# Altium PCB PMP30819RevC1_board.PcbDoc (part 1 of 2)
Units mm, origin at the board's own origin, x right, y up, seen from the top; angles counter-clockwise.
Board outline 73.66 x 66.04 mm, 4 copper layers (Top Layer, Layer 1, Layer 2, Bottom Layer), stack 1.787 mm thick; 100 components, 30 nets, 255 pads, 105 vias.
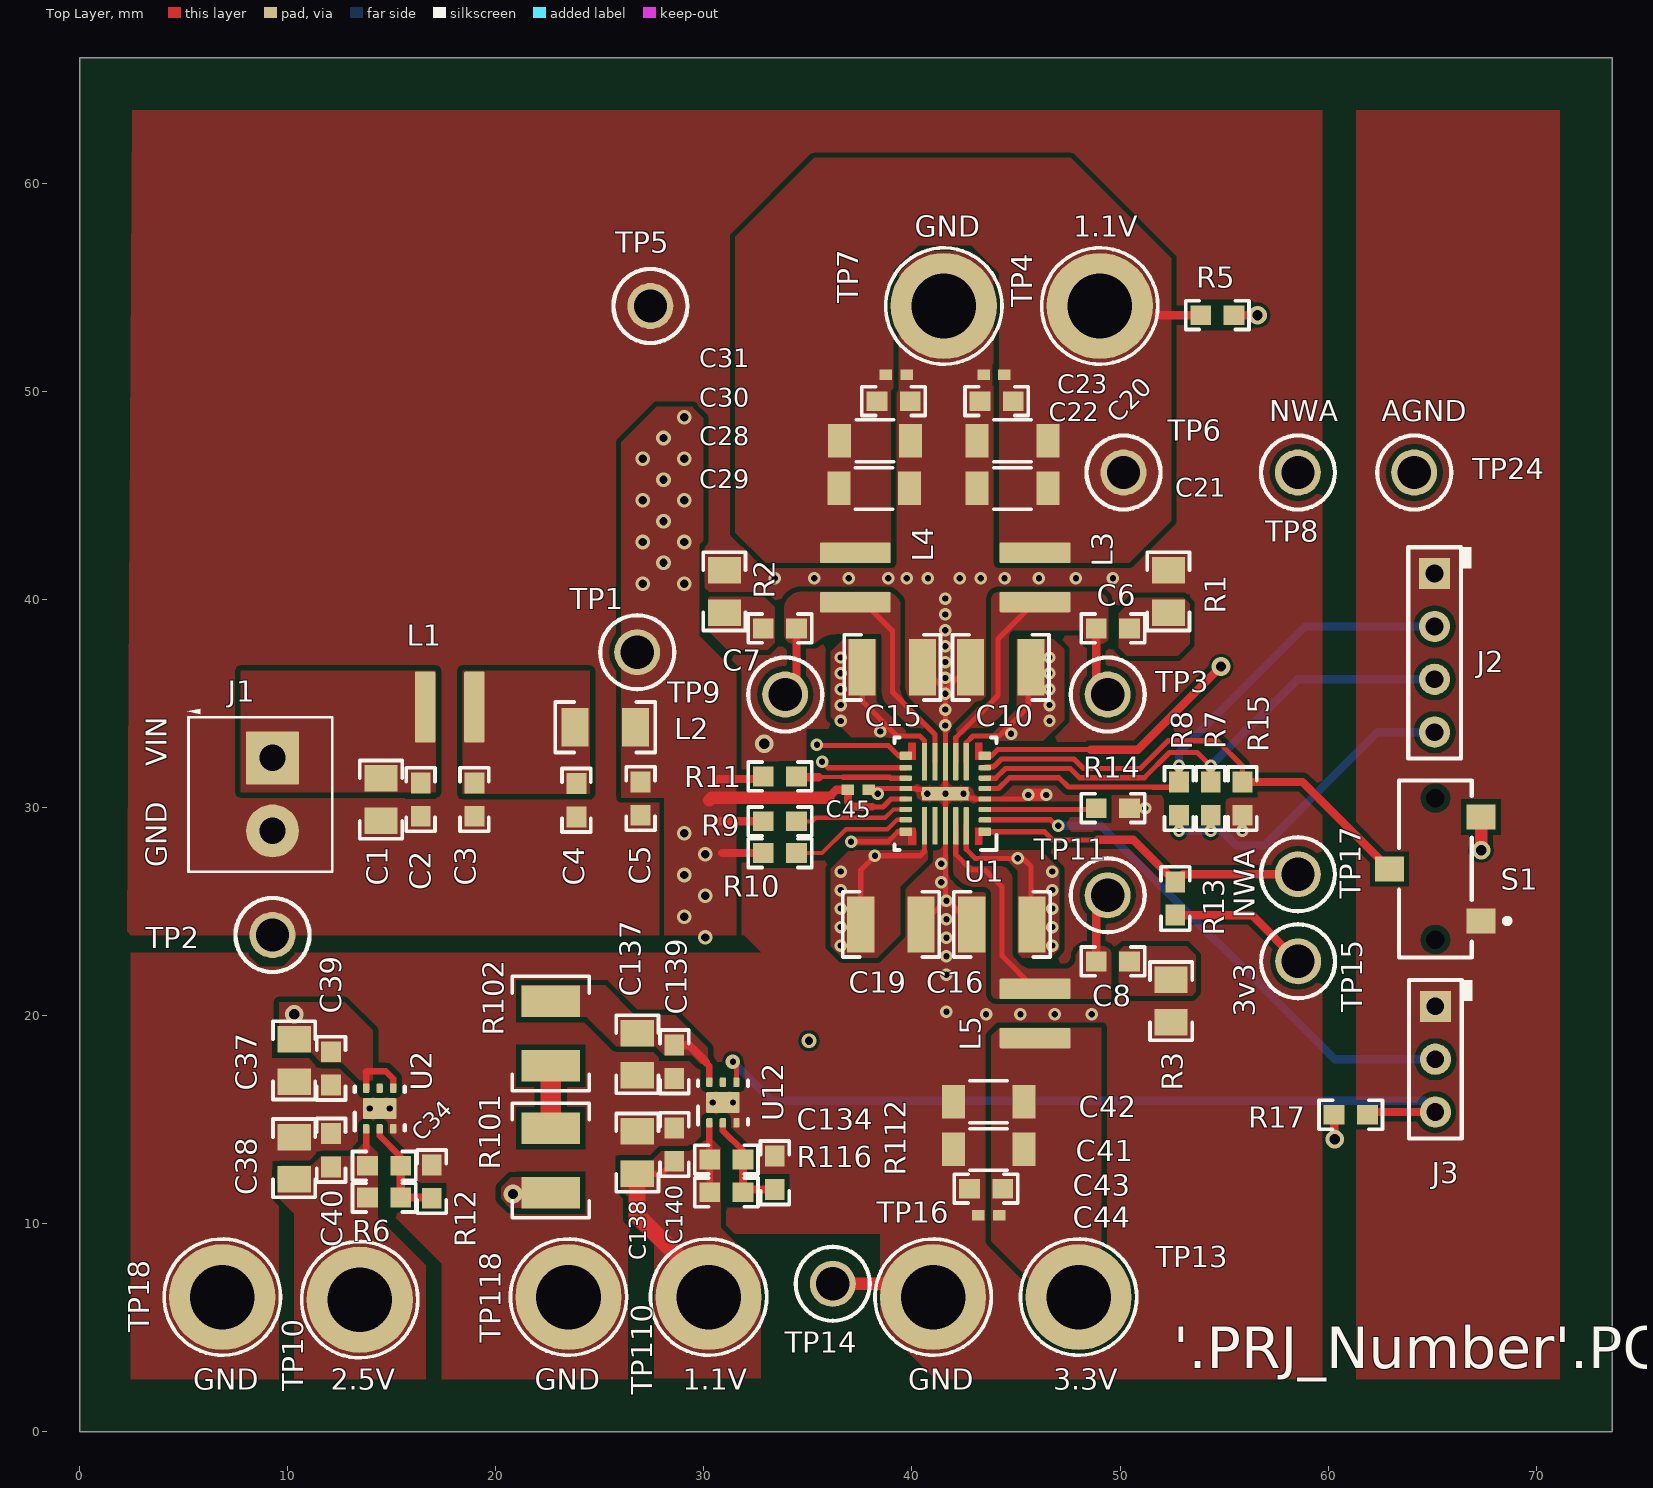
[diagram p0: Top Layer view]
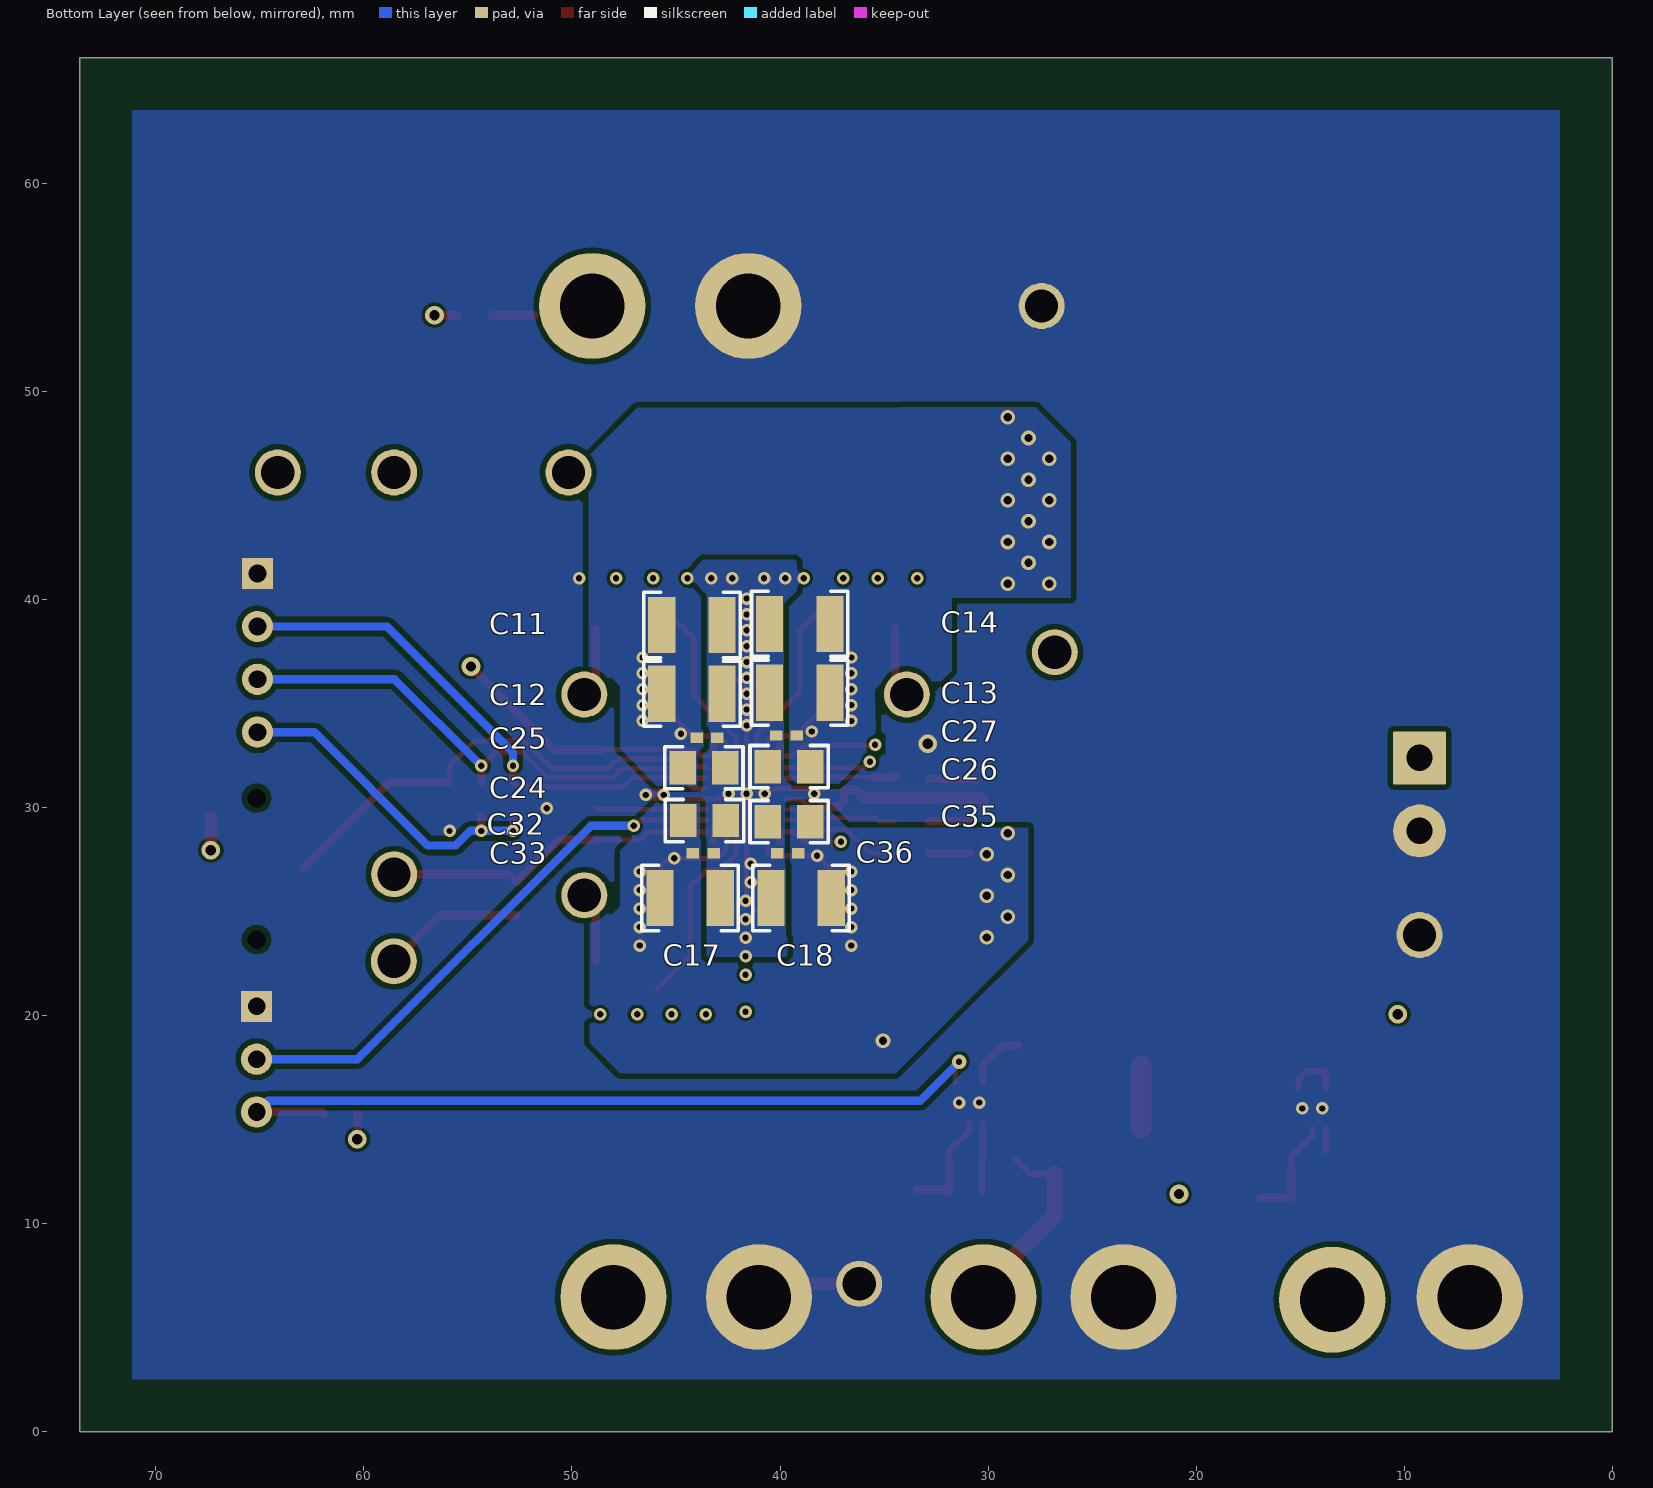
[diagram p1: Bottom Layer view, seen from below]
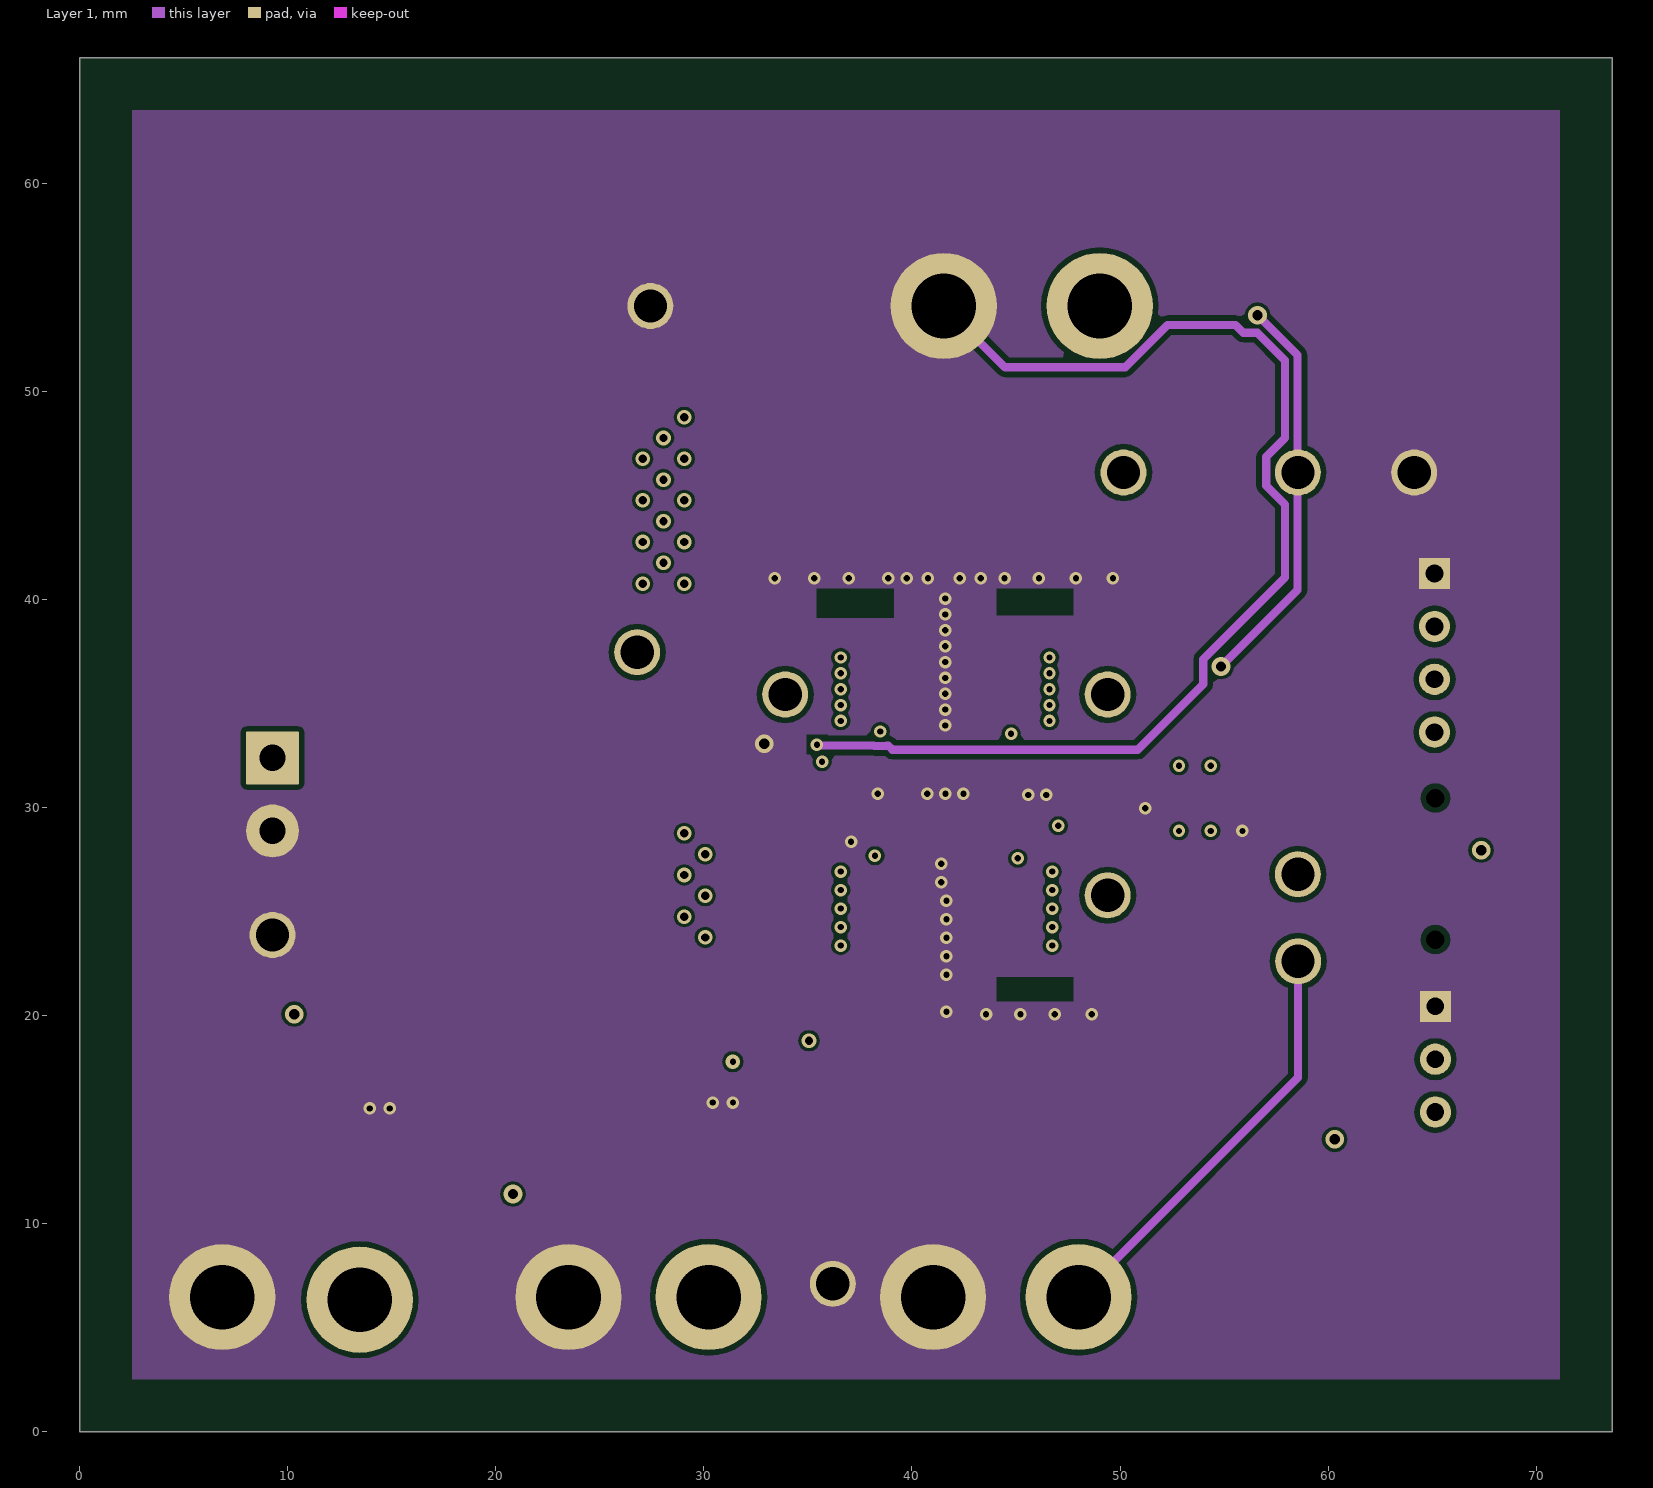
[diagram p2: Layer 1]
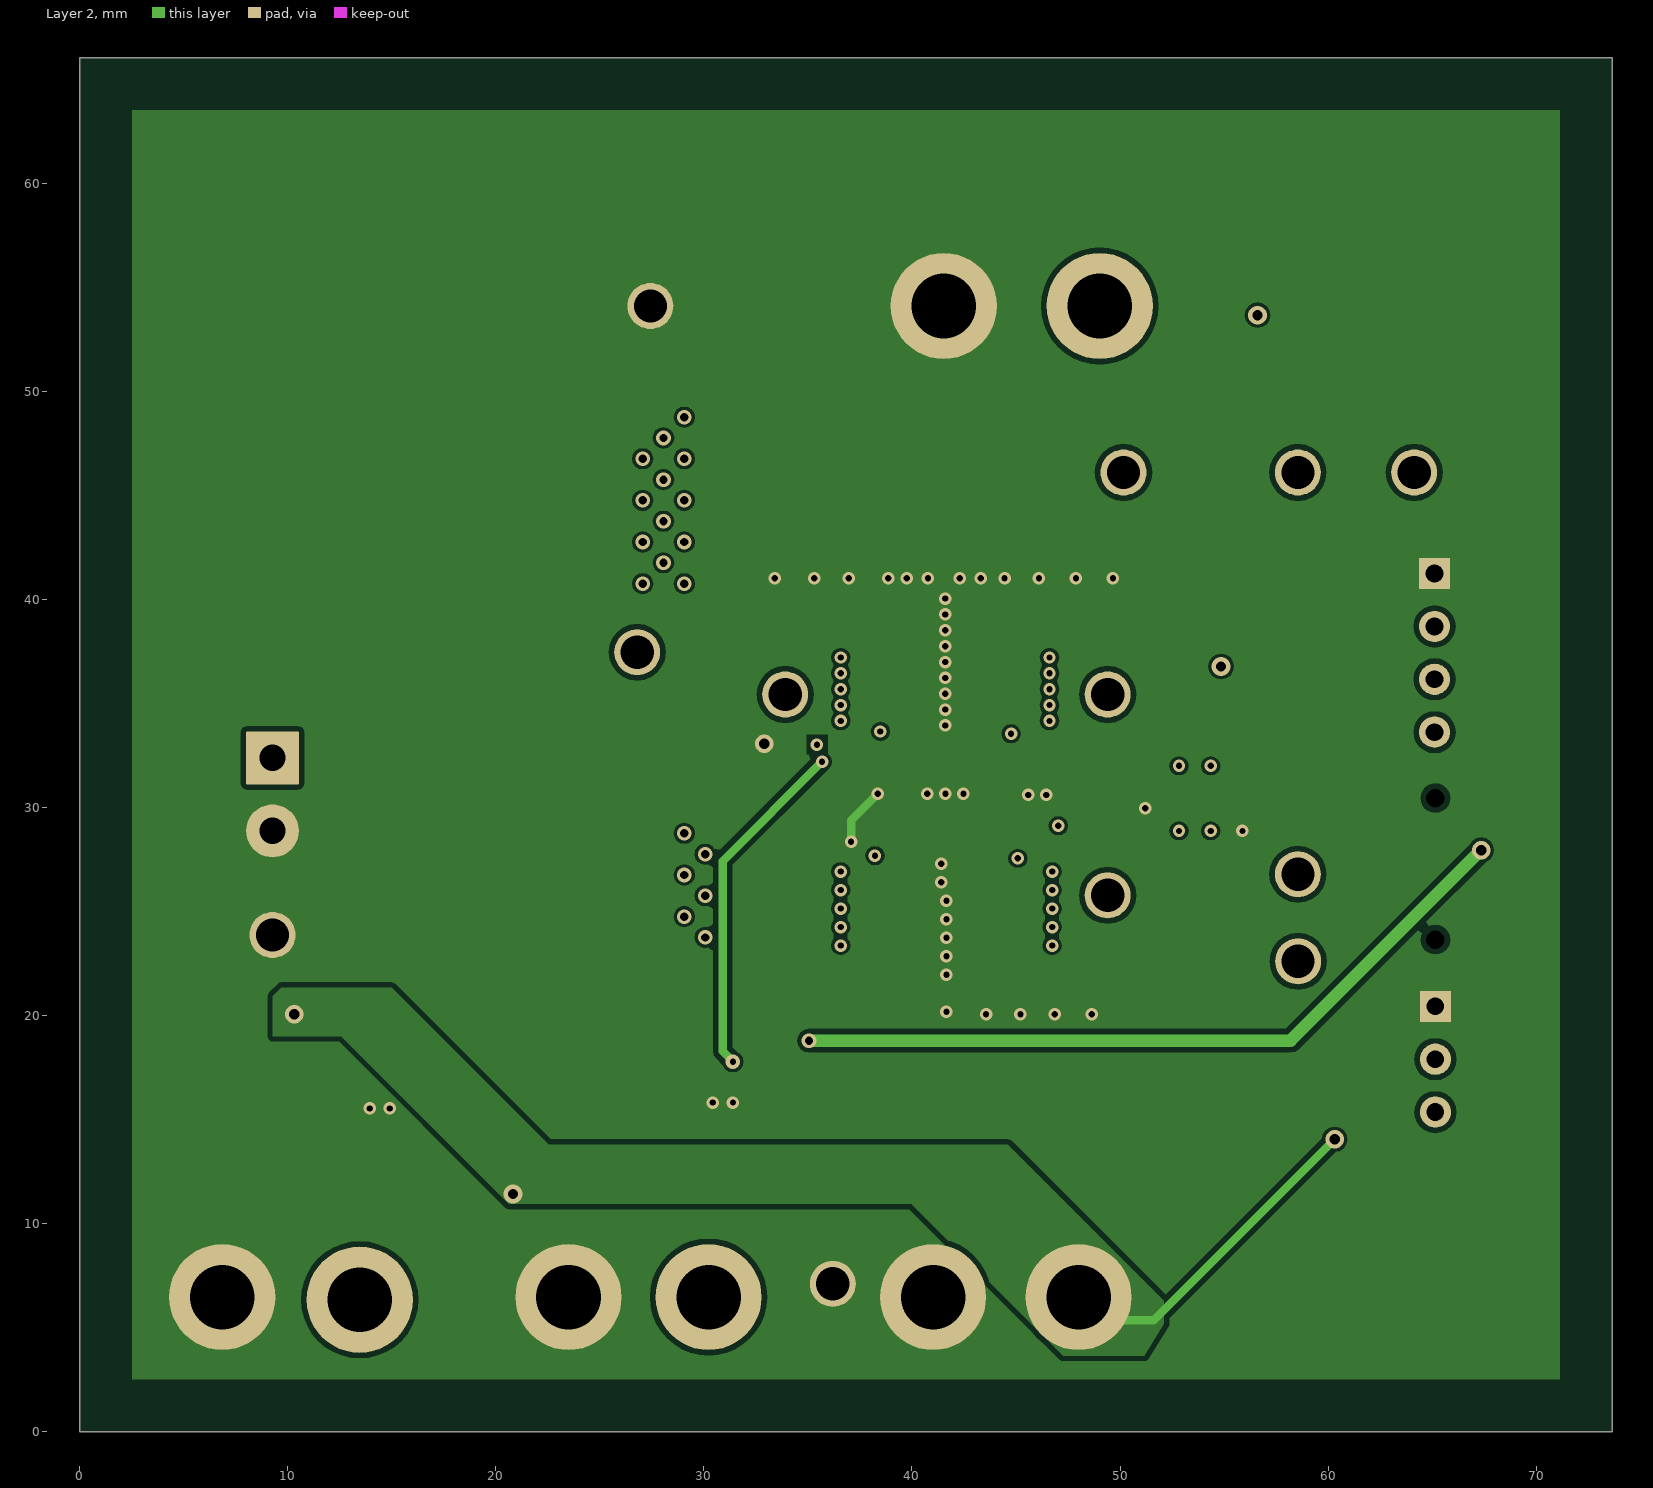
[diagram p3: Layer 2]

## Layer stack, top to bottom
Top Solder: solder mask 0.0102, Solder Resist, Dk 3.5
Top Layer: signal copper 0.0356
Dielectric 1: prepreg 0.0711, PP-006, Dk 4.1
Layer 1: signal copper 0.035
Dielectric1: core 1.5037, FR-4, Dk 4.8
Layer 2: signal copper 0.035
Dielectric 2: prepreg 0.0711, PP-006, Dk 4.1
Bottom Layer: signal copper 0.0356
Bottom Solder: solder mask 0.0102, Solder Resist, Dk 3.5

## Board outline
0,0 0,66.04 73.66,66.04 73.66,0

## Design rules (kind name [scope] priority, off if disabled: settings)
AcuteAngle [All] p1: minimum=4.50000000000000E+0001 checktracksonly=FALSE
AssemblyTestPointUsage [All] p1: valid=2
BoardOutlineClearance BoardOutlineClearance_MountingHoles [OnCopper and InComponentClass('Mounting Holes')] p1: gap=1 ignorepadtopadclearanceinfootprint=FALSE
BoardOutlineClearance BoardOutlineClearance_Poly [OnCopper and IsPoly] p2: gap=0.635 ignorepadtopadclearanceinfootprint=FALSE
BoardOutlineClearance [OnCopper and Not InComponentClass('Logo') and not InComponentClass('FiducialMark') and not InRegion(1000,500,4000,800) and not InPoly] p3: gap=1.905 ignorepadtopadclearanceinfootprint=FALSE
Clearance Clearance_Keepouts [((IsTrack Or IsArc) And Not InPoly) And IsFree and IsKeepOut vs ((IsTrack Or IsArc) And Not InPoly) And IsFree and IsKeepOut] p1: gap=0 ignorepadtopadclearanceinfootprint=FALSE
Clearance Clearance_Poly [InPolygon] p2: gap=0.254 ignorepadtopadclearanceinfootprint=TRUE except(0.15: Via-Fill Via-Poly Via-Region)
Clearance Clearance_FiducialMark [IsKeepOut and InComponentClass('FiducialMark') vs IsPad and InComponentClass('FiducialMark')] p3: gap=0 ignorepadtopadclearanceinfootprint=FALSE
Clearance [All] p4: gap=0.2 ignorepadtopadclearanceinfootprint=TRUE
ComponentClearance ComponentClearance_MountingHoles_FiducialMarks [InComponentClass('Mounting Holes') vs InComponentClass('FiducialMark')] p1: gap=1.27 collisioncheckmode=3 verticalgap=0.254 showdistances=FALSE
ComponentClearance ComponentClearance_Shunt [InComponentClass('Header') vs InComponentClass('Shunt')] p2: gap=0 collisioncheckmode=3 verticalgap=0 showdistances=FALSE
ComponentClearance ComponentClearance_Logo [InComponentClass('Logo')] p3: gap=1.27 collisioncheckmode=3 verticalgap=0.254 showdistances=FALSE
ComponentClearance ComponentClearance_ScrewToNut [(HasFootprint('NY PMS 440 0025 PH')) vs (HasFootprint('Keystone_1902C'))] p4: gap=0.127 collisioncheckmode=3 verticalgap=0.254 showdistances=FALSE
ComponentClearance ComponentClearance_MountingHoles [InComponentClass('Mounting Holes')] p5: gap=6.35 collisioncheckmode=3 verticalgap=2540 showdistances=FALSE
ComponentClearance ComponentClearance_SmallPassives [HasFootprint('0201*') or HasFootprint('0402*') or HasFootprint('0508') or HasFootprint('0603*') or HasFootprint('0612') or HasFootprint('0805*') or HasFootprint('0815*') or HasFootprint('0830*') or HasFootprint('1206*') or HasFootprint('1210*') or HasFootprint('1808*') or HasFootprint('1812*') or HasFootprint('1825*') or HasFootprint('2010*') or HasFootprint('2220*') or HasFootprint('2225*') or HasFootprint('2512*') or HasFootprint('2728*') or HasFootprint('3518*') vs HasFootprint('0201*') or HasFootprint('0402*') or HasFootprint('0508') or HasFootprint('0603*') or HasFootprint('0612') or HasFootprint('0805*') or HasFootprint('0815*') or HasFootprint('0830*') or HasFootprint('1206*') or HasFootprint('1210*') or HasFootprint('1808*') or HasFootprint('1812*') or HasFootprint('1825*') or HasFootprint('2010*') or HasFootprint('2220*') or HasFootprint('2225*') or HasFootprint('2512*') or HasFootprint('2728*') or HasFootprint('3518*')] p6: gap=0.38 collisioncheckmode=3 verticalgap=0.254 showdistances=FALSE
ComponentClearance ComponentClearance_THtoSMT [IsThruComponent vs IsSMTComponent] p7: gap=1.016 collisioncheckmode=3 verticalgap=0.762 showdistances=FALSE
ComponentClearance ComponentClearance_THtoTH [IsThruComponent vs IsThruComponent] p8: gap=0.762 collisioncheckmode=3 verticalgap=0.762 showdistances=FALSE
ComponentClearance [All] p9: gap=0.762 collisioncheckmode=3 verticalgap=0.254 showdistances=FALSE
DiffPairsRouting [All] p1: maxlimit=2.54 minlimit=0.254 mostfreqgap=0.254 toplayer_minwidth=0.381 toplayer_maxwidth=0.381 toplayer_prefwidth=0.381 midlayer1_minwidth=0.381 midlayer1_maxwidth=0.381 midlayer1_prefwidth=0.381 midlayer2_minwidth=0.381 midlayer2_maxwidth=0.381 midlayer2_prefwidth=0.381 bottomlayer_minwidth=0.381 bottomlayer_maxwidth=0.381 bottomlayer_prefwidth=0.381 maxuncoupledlength=25.4
FabricationTestPointUsage TestPointUsage [All] p1: valid=2 allowmultiple=FALSE
FabricationTestpoint Testpoint [All] p1: side=3 testpointundercomponent=TRUE minsize=1.016 maxsize=2.54 preferedsize=1.524 minholesize=0 maxholesize=1.016 preferedholesize=0.813 testpointgrid=0.025 allowsidetop=TRUE allowsidebottom=TRUE usegrid=TRUE gridtolerance=0
FanoutControl Fanout_LCC [IsLCC] p1: bgadir=Out bgaviamode=Centered fanoutstyle=Auto fanoutdirection=Alternating viagrid=0.025 // Fanout_LCC (Default Rule)
FanoutControl Fanout_BGA [IsBGA] p2: bgadir=Out bgaviamode=Centered fanoutstyle=Auto fanoutdirection=Alternating viagrid=0.025 // Fanout_BGA (Default Rule)
FanoutControl Fanout_Default [All] p4: bgadir=Out bgaviamode=Centered fanoutstyle=Auto fanoutdirection=Alternating viagrid=0.025 // Fanout_Default (Default Rule)
FanoutControl Fanout_Small [(CompPinCount < 5)] p5: bgadir=Out bgaviamode=Centered fanoutstyle=Auto fanoutdirection=OutThenIn viagrid=0.025 // Fanout_Small (Default Rule)
HoleSize [All] p1: absolutevalues=TRUE maxlimit=6.375 minlimit=0.3 maxpercent=80.000 minpercent=20.000
MinimumAnnularRing MinimumAnnularRing_ThermalPadVias [IsVia and InAnyComponent] p1: minimumring=0.15
MinimumAnnularRing [All] p2: minimumring=0.15
MinimumSolderMaskSliver MinimumSolderMaskSliver_Logo [InComponentClass('Logo') vs InComponentClass('Logo')] p1: minsoldermaskwidth=0.018
MinimumSolderMaskSliver [All] p2: minsoldermaskwidth=0.1
PlaneConnect [All] p1: planeconnectstyle=Relief reliefexpansion=0.254 reliefentries=4 reliefconductorwidth=0.254 reliefairgap=0.254
PolygonConnect PolygonConnect_TP24 [InComponent('TP24') vs OnBottomLayer or OnTopLayer or OnLayer('Layer 2')] p1: thpad.connectstyle=NoConnect thpad.reliefconductorwidth=0.254 thpad.reliefentries=4 thpad.polygonreliefangle="90 Angle" thpad.airgapwidth=0.254 smdpad.connectstyle=Direct smdpad.reliefconductorwidth=0.254 smdpad.reliefentries=4 smdpad.polygonreliefangle="90 Angle" smdpad.airgapwidth=0.254 via.connectstyle=Direct via.reliefconductorwidth=0.254 via.reliefentries=4 via.polygonreliefangle="90 Angle" via.airgapwidth=0.254
PolygonConnect [All] p2: connectstyle=Direct reliefconductorwidth=0.254 reliefentries=4 polygonreliefangle="90 Angle" airgapwidth=0.254
RoutingVias ThermalPadVias [IsVia and InAnyComponent] p1: holewidth=0.2 width=0.5 viastyle="Through Hole" minholewidth=0.2 minwidth=0.5 maxholewidth=0.33 maxwidth=0.6
RoutingVias [All] p2: holewidth=0.5 width=0.9 viastyle="Through Hole" minholewidth=0.3 minwidth=0.6 maxholewidth=1.016 maxwidth=1.651
SilkToBoardRegionClearance [Not ((IsComment or IsDesignator) And (Hide <> 'False')) and not InRegion(1000,500,4000,800)] p1:
SilkToSilkClearance SilkToSilkClearance_Pb-FreeLogo [(HasFootprint('Pb-Free_Overlay_Medium') OR HasFootprint('Pb-Free_Overlay_Small')) vs (HasFootprint('Pb-Free_Overlay_Medium') OR HasFootprint('Pb-Free_Overlay_Small'))] p1: silktosilkclearance=0
SilkToSilkClearance [All] p2: silktosilkclearance=0.1
SilkToSolderMaskClearance SilkToComponentPadClearance [(IsPad or IsFill or IsRegion) and InAnycomponent] p1: minsilkscreentomaskgap=0.127 clearancetoexposedcopper=TRUE
SilkToSolderMaskClearance "Silk to Solder Mask Opening" [All] p2: minsilkscreentomaskgap=0.1 clearancetoexposedcopper=FALSE
SolderMaskExpansion [All] p1: expansion=0.05 istentingtop=FALSE
UnRoutedNet [All] p1: checkbadconnections=TRUE
Width [All] p1: maxlimit=2.54 minlimit=0.152 preferedwidth=0.254 checkconnectedcopper=TRUE
14 further rules are at their usual default settings.

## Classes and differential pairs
component class Header: J2 J3

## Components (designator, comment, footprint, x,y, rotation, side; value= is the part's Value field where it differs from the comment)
C1 "CL21B106KOQNNNE" 0805_HV 14.486,30.386 r270 top value=10uF
C2 "GRM188R71C105KA12D" 0603 16.391,30.386 r270 top value=1uF
C3 "GRM188R71C105KA12D" 0603 18.973,30.386 r270 top value=1uF
C4 "GRM188R71C103KA01D" 0603 23.876,30.353 r270 top value=0.01uF
C5 "GRM188R71C103KA01D" 0603 26.958,30.431 r270 top value=0.01uF
C6 "GRM188R71H391KA01D" 0603 49.657,38.608 r0 top value=390pF
C7 "GRM188R71H391KA01D" 0603 33.655,38.608 r180 top value=390pF
C8 "GRM188R71H391KA01D" 0603 49.657,22.606 r0 top value=390pF
C10 "LMK325B7476MM-TR" 1210_270 44.264,36.74 r180 top value=47uF
C11 "LMK325B7476MM-TR" 1210_270 44.234,38.772 r180 bottom value=47uF
C12 "LMK325B7476MM-TR" 1210_270 44.234,35.47 r180 bottom value=47uF
C13 "LMK325B7476MM-TR" 1210_270 39.057,35.521 r0 bottom value=47uF
C14 "LMK325B7476MM-TR" 1210_270 39.057,38.823 r0 bottom value=47uF
C15 "LMK325B7476MM-TR" 1210_270 39.057,36.74 r180 top value=47uF
C16 "LMK325B7476MM-TR" 1210_270 44.323,24.384 r180 top value=47uF
C17 "LMK325B7476MM-TR" 1210_270 44.323,25.654 r180 bottom value=47uF
C18 "LMK325B7476MM-TR" 1210_270 38.989,25.654 r0 bottom value=47uF
C19 "LMK325B7476MM-TR" 1210_270 38.989,24.384 r0 top value=47uF
C20 "GRJ31CR71A226KE12L" 1206_190 44.831,47.625 r180 top value=22uF
C21 "GRJ31CR71A226KE12L" 1206_190 44.831,45.339 r180 top value=22uF
C22 "GCM188R71C104KA37J" 0603 44.069,49.53 r0 top value=0.1uF
C23 "CGA2B2X7R1H332K050BA" 0402L 43.942,50.8 r180 top value=3300pF
C24 "CL21B106KOQNNNE" 0805_HV 43.655,31.913 r180 bottom value=10uF
C25 "C0402C104K4RACAUTO" 0402L 43.505,33.363 r0 bottom value=0.1uF
C26 "CL21B106KOQNNNE" 0805_HV 39.565,31.965 r0 bottom value=10uF
C27 "C0402C104K4RACAUTO" 0402L 39.692,33.463 r0 bottom value=0.1uF
C28 "GRJ31CR71A226KE12L" 1206_190 38.227,47.625 r0 top value=22uF
C29 "GRJ31CR71A226KE12L" 1206_190 38.184,45.339 r0 top value=22uF
C30 "GCM188R71C104KA37J" 0603 39.116,49.53 r180 top value=0.1uF
C31 "CGA2B2X7R1H332K050BA" 0402L 39.243,50.8 r0 top value=3300pF
C32 "CL21B106KOQNNNE" 0805_HV 43.629,29.374 r180 bottom value=10uF
C33 "C0402C104K4RACAUTO" 0402L 43.688,27.813 r0 bottom value=0.1uF
C34 "GRM188R71C103KA01D" 0603 14.639,12.784 r0 top value=0.01uF
C35 "CL21B106KOQNNNE" 0805_HV 39.565,29.323 r0 bottom value=10uF
C36 "C0402C104K4RACAUTO" 0402L 39.624,27.813 r0 bottom value=0.1uF
C37 "CL21B106KOQNNNE" 0805_HV 10.311,17.849 r270 top value=10uF
C38 "CL21B106KOQNNNE" 0805_HV 10.311,13.15 r90 top value=10uF
C39 "GCM188R71C104KA37J" 0603 12.089,17.468 r90 top value=0.1uF
C40 "GCM188R71C104KA37J" 0603 12.089,13.531 r270 top value=0.1uF
C41 "GRJ31CR71A226KE12L" 1206_190 43.689,13.576 r180 top value=22uF
C42 "GRJ31CR71A226KE12L" 1206_190 43.689,15.862 r180 top value=22uF
C43 "GCM188R71C104KA37J" 0603 43.561,11.684 r0 top value=0.1uF
C44 "CGA2B2X7R1H332K050BA" 0402L 43.688,10.414 r180 top value=3300pF
C45 "C0402C104K4RACAUTO" 0402L 37.424,30.861 r0 top value=0.1uF
C134 "GRM188R71C103KA01D" 0603 31.082,13.085 r0 top value=0.01uF
C137 "CL21B106KOQNNNE" 0805_HV 26.804,18.145 r270 top value=10uF
C138 "CL21B106KOQNNNE" 0805_HV 26.804,13.423 r90 top value=10uF
C139 "GCM188R71C104KA37J" 0603 28.582,17.784 r90 top value=0.1uF
C140 "GCM188R71C104KA37J" 0603 28.582,13.804 r270 top value=0.1uF
J1 "ED555/2DS" TERM_BLK_ED555-2DS 9.271,32.385 r270 top
J2 "800-10-004-10-001000" Mill-Max_800-10-004-10-001000 65.113,37.434 r270 top
J3 "800-10-003-10-001000" Mill-Max_800-10-003-10-001000 65.151,17.907 r270 top
L1 "XGL4020-471MEC" FP-XGL4020-471MEC_SMT_4MM0_4MM0-MFG 17.788,34.831 r0 top
L2 "HI1206T161R-10" 1206 25.258,33.86 r0 top value="160 ohm"
L3 "XGL4020-471MEC" FP-XGL4020-471MEC_SMT_4MM0_4MM0-MFG 45.915,41.058 r90 top
L4 "XGL4020-471MEC" FP-XGL4020-471MEC_SMT_4MM0_4MM0-MFG 37.279,41.058 r90 top
L5 "XGL4020-471MEC" FP-XGL4020-471MEC_SMT_4MM0_4MM0-MFG 45.915,20.103 r270 top
R1 "CRCW08053R90JNEA" 0805_HV 52.324,40.386 r270 top value=3.9
R2 "CRCW08053R90JNEA" 0805_HV 30.988,40.386 r270 top value=3.9
R3 "CRCW08053R90JNEA" 0805_HV 52.451,20.701 r90 top value=3.9
R5 "CRCW060347R0JNEA" 0603 54.674,53.662 r180 top value=47
R6 "CRCW060319K6FKEA" 0603 14.639,11.26 r180 top value=19.6k
R7 "CRCW06032K20JNEA" 0603 54.356,30.428 r90 top value=2.2k
R8 "CRCW06032K20JNEA" 0603 52.832,30.428 r90 top value=2.2k
R9 "CRCW0603100KFKEA" 0603 33.655,29.337 r0 top value=100k
R10 "CRCW0603100KFKEA" 0603 33.655,27.813 r0 top value=100k
R11 "DNP" 0603 33.655,31.496 r0 top value=100k
R12 "CRCW06035K49FKEA" 0603 16.925,12.022 r270 top value=5.49k
R13 "CRCW060347R0JNEA" 0603 52.656,25.63 r270 top value=47
R14 "CRCW060310K0JNEA" 0603 49.657,29.972 r0 top value=10k
R15 "DNP" 0603 55.88,30.428 r90 top value=100k
R17 "CRCW060310K0JNEA" 0603 61.087,15.24 r180 top value=10k
R101 "ERJ-14BQF2R0U" 1210M 22.639,13.044 r90 top value=2.00
R102 "ERJ-14BQF2R0U" 1210M 22.639,19.14 r90 top value=2.00
R112 "CRCW06035K49FKEA" 0603 33.408,12.45 r270 top value=5.49k
R116 "CRCW06035K49FKEA" 0603 31.082,11.51 r180 top value=5.49k
S1 "CL-SB-12B-01T" SW_CL-SB-12B-01 65.151,27.051 r180 top
TP1 "5010" Keystone5010 26.797,37.465 r0 top
TP2 "5011" Keystone5011 9.271,23.876 r0 top
TP3 "SW_0" Keystone5012 49.403,35.433 r180 top
TP4 "1.1VD" Keystone1503-2 49.022,54.102 r180 top value=Double
TP5 "GND" Keystone5011 27.433,54.102 r0 top
TP6 "1V1D" Keystone5010 50.165,46.101 r180 top
TP7 "GND" Keystone1503-2 41.529,54.102 r180 top value=Double
TP8 "5014" Keystone5014 58.547,46.101 r180 top
TP9 "SW_1" Keystone5012 33.909,35.433 r180 top
TP10 "2.5VA" Keystone1503-2 13.462,6.35 r180 top value=Double
TP11 "SW_2" Keystone5012 49.403,25.781 r180 top
TP13 "3.3V" Keystone1503-2 48.006,6.477 r0 top value=Double
TP14 "GND" Keystone5011 36.195,7.112 r0 top
TP15 "3V3" Keystone5010 58.553,22.611 r0 top
TP16 "GND" Keystone1503-2 41.015,6.477 r0 top value=Double
TP17 "5014" Keystone5014 58.547,26.797 r0 top
TP18 "GND" Keystone1503-2 6.858,6.477 r180 top value=Double
TP24 "5011" Keystone5011 64.135,46.101 r0 top
TP110 "1.1VA" Keystone1503-2 30.226,6.477 r0 top value=Double
TP118 "GND" Keystone1503-2 23.495,6.477 r0 top value=Double
U1 "LP87563BRNFRQ1" RNF0026C 41.605,30.663 r180 top
U2 "TPS74501PDRVR" DRV0006A 14.423,15.537 r90 top
U12 "TPS74501PDRVR" DRV0006A 30.913,15.823 r90 top

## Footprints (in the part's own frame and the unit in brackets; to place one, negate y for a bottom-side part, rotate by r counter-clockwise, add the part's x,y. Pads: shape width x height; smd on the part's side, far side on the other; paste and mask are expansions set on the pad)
0402L [mm] "0402 from SM-752 data"
  rect 0.6x0.5 smd: 1(-0.5,0) 2(0.5,0)
  body extent -0.55,-0.3 0.55,0.3, height 0.6
0603 [mm] "0603 from SM-752 data"
  rect 1x0.95 smd: 1(-0.8,0) 2(0.8,0)
  silkscreen extent -1.52,-0.69 1.52,0.69, body extent -0.87,-0.47 0.87,0.47, height 1
0805_HV [mil] "0805 with 30mil clearance between pads"
  rect 50x63 smd: 1(-40,0) 2(40,0)
  silkscreen extent -74,-40 74,40, body extent -43,-29 43,29, height 57
1206 [mm] "1206 from SM-752 data"
  rect 1.3x1.85 smd: 1(-1.45,0) 2(1.45,0)
  silkscreen extent -2.4,-1.21 2.4,1.21, body extent -1.7,-0.9 1.7,0.9, height 1.35
1206_190 [mm] "1206_190"
  rect 1.1x1.6 smd: 1(-1.7,0) 2(1.7,0)
  silkscreen extent -0.9,-1 0.9,1, body extent -1.75,-0.95 1.75,0.95, height 1.9
1210_270 [mm] "1210"
  rect 1.3x2.7 smd: 1(-1.45,0) 2(1.45,0)
  silkscreen extent -2.32,-1.57 2.32,1.57, body extent -1.7,-1.35 1.7,1.35, height 2.7
1210M [mm] "1210 from SM-752 data"
  rect 1.5x2.8 smd: 1(-1.55,0) 2(1.55,0)
  silkscreen extent -2.75,-1.85 2.75,1.85, body extent -1.7,-1.35 1.7,1.35, height 1.35
DRV0006A [mm] "SON, 6-Leads, Body 2x2mm, Pitch 0.65mm, Thermal Pad 1.6x1mm, TI Recommended"
  rrect33% 0.45x0.3 smd: 1(-0.975,0.65) 2(-0.975,0) 3(-0.975,-0.65) 4(0.975,-0.65) 5(0.975,0) 6(0.975,0.65)
  rrect14% 1x0.7 on Top Paste: 7(0,0.45) 7(0,-0.45)
  rrect10% 1x1.6 smd paste-0.5: 7(0,0)
  silkscreen extent -1.05,-1.2 1.05,1.2, body extent -1.05,-1.05 1.05,1.05, height 0.81
FP-XGL4020-471MEC_SMT_4MM0_4MM0-MFG [mm]
  rrect10% 0.98x3.4 smd paste+0 mask+0: 1(-1.185,0) 2(1.185,0)
  body extent -2.25,-2.25 2.25,2.25, height 0.25
Keystone1503-2 [mm] "Double Turret"
  round 5.1 hole 3.1: 1(0,0)
  silkscreen extent -2.79,-2.79 2.79,2.79, body extent -2.4,-2.4 2.38,2.4, height 9.22
Keystone5010 [mil] "Keystone Multipurpose loops"
  round 87 hole 63: 1(0,0)
  silkscreen extent -70,-70 70,70, body extent -63,-63 63,62, height 319
Keystone5011 [mil] "Keystone Multipurpose loops"
  round 87 hole 63: 1(0,0)
  silkscreen extent -70,-70 70,70, body extent -63,-63 63,62, height 319
Keystone5012 [mil] "Keystone Multipurpose loops"
  round 87 hole 63: 1(0,0)
  silkscreen extent -70,-70 70,70, body extent -63,-63 63,62, height 319
Keystone5014 [mil] "Keystone Multipurpose loops"
  round 87 hole 63: 1(0,0)
  silkscreen extent -70,-70 70,70, body extent -63,-63 63,62, height 319
Mill-Max_800-10-003-10-001000 [mm] "Mill-Max"
  rect 1.5x1.5 hole 0.85: 1(-2.54,0)
  round 1.5 hole 0.85: 2(0,0) 3(2.54,0)
  silkscreen extent -3.81,-1.27 3.81,1.78, body extent -3.81,-1.27 3.81,1.27, height 8.13
Mill-Max_800-10-004-10-001000 [mm] "Mill-Max"
  rect 1.5x1.5 hole 0.85: 1(-3.81,0)
  round 1.5 hole 0.85: 2(-1.27,0) 3(1.27,0) 4(3.81,0)
  silkscreen extent -5.08,-1.27 5.08,1.78, body extent -5.08,-1.27 5.08,1.27, height 8.13
RNF0026C [mm] "QFN, 26-Leads, Body 4x4.5mm, Pitch 0.5mm"
  rrect25% 0.6x0.4 smd paste-0.3: 1(-1.9,1.825) 8(-1.9,-1.825) 14(1.9,-1.825) 21(1.9,1.825)
  rrect40% 0.6x0.25 smd paste+0: 2(-1.9,1.25) 3(-1.9,0.75) 4(-1.9,0.25) 5(-1.9,-0.25) 6(-1.9,-0.75) 7(-1.9,-1.25) 15(1.9,-1.25) 16(1.9,-0.75) 17(1.9,-0.25) 18(1.9,0.25) 19(1.9,0.75) 20(1.9,1.25)
  rrect40% 0.25x1.82 smd paste-1: 9(-1,-1.54) 10(-0.5,-1.54) 11(0,-1.54) 12(0.5,-1.54) 13(1,-1.54) 22(1,1.54) 23(0.5,1.54) 24(0,1.54) 25(-0.5,1.54) 26(-1,1.54)
  rrect15% 2.24x0.66 smd paste-1: 27(0,0)
  rrect33% 0.6x0.3 on Top Paste: ""(-1.9,1.775) ""(-1.9,-1.775) ""(1.9,1.775) ""(1.9,-1.775)
  rrect33% 0.3x0.825 on Top Paste: ""(-1.575,2.037) ""(-1.575,-2.037) ""(1.575,2.037) ""(1.575,-2.037)
  rrect40% 0.25x0.81 on Top Paste: ""(-1,1.035) ""(-1,2.045) ""(-1,-2.045) ""(-1,-1.035) ""(-0.5,2.045) ""(-0.5,1.035) ""(-0.5,-1.035) ""(-0.5,-2.045) ""(0,2.045) ""(0,1.035) ""(0,-1.035) ""(0,-2.045) ""(0.5,2.045) ""(0.5,1.035) ""(0.5,-1.035) ""(0.5,-2.045) ""(1,1.035) ""(1,2.045) ""(1,-2.045) ""(1,-1.035)
  rrect15% 0.98x0.66 on Top Paste: ""(-0.59,0) ""(0.59,0)
  Top Layer region: -1.775,-2.4 -1.775,-1.675 -1.771,-1.656 -1.76,-1.64 -1.744,-1.629 -1.725,-1.625 -1.725,-1.625 -1.475,-1.625 -1.456,-1.629 -1.44,-1.64 -1.429,-1.656 -1.425,-1.675 -1.425,-1.675 -1.425,-2.4 -1.429,-2.419 -1.44,-2.435 -1.456,-2.446 -1.475,-2.45 -1.475,-2.45 -1.725,-2.45 -1.744,-2.446 -1.76,-2.435 -1.771,-2.419 -1.775,-2.4
  Top Layer region: 1.425,-2.4 1.425,-1.675 1.429,-1.656 1.44,-1.64 1.456,-1.629 1.475,-1.625 1.475,-1.625 1.725,-1.625 1.744,-1.629 1.76,-1.64 1.771,-1.656 1.775,-1.675 1.775,-1.675 1.775,-2.4 1.771,-2.419 1.76,-2.435 1.744,-2.446 1.725,-2.45 1.725,-2.45 1.475,-2.45 1.456,-2.446 1.44,-2.435 1.429,-2.419 1.425,-2.4
  Top Layer region: 1.425,1.675 1.425,2.4 1.429,2.419 1.44,2.435 1.456,2.446 1.475,2.45 1.475,2.45 1.725,2.45 1.744,2.446 1.76,2.435 1.771,2.419 1.775,2.4 1.775,2.4 1.775,1.675 1.771,1.656 1.76,1.64 1.744,1.629 1.725,1.625 1.725,1.625 1.475,1.625 1.456,1.629 1.44,1.64 1.429,1.656 1.425,1.675
  Top Layer region: -1.775,1.675 -1.775,2.4 -1.771,2.419 -1.76,2.435 -1.744,2.446 -1.725,2.45 -1.725,2.45 -1.475,2.45 -1.456,2.446 -1.44,2.435 -1.429,2.419 -1.425,2.4 -1.425,2.4 -1.425,1.675 -1.429,1.656 -1.44,1.64 -1.456,1.629 -1.475,1.625 -1.475,1.625 -1.725,1.625 -1.744,1.629 -1.76,1.64 -1.771,1.656 -1.775,1.675
  silkscreen extent -2.45,-2.7 2.45,2.7, body extent -2,-2.25 2,2.25, height 0.9
SW_CL-SB-12B-01 [mm] "SMD, 3-Leads, Body 8.5x3.5mm, Pitch 2.5mm"
  rect 1.4x1.2 smd: 1(-2.2,2.5) 2(2.2,0) 3(-2.2,-2.5)
  round 0 hole 0.9 unplated: MH1(0,3.4) MH2(0,-3.4)
  silkscreen extent -3.58,-4.25 1.75,4.25, body extent -1.75,-4.25 1.75,4.25, height 5.5
TERM_BLK_ED555-2DS [mil]
  rrect4% 100x100 hole 50: 1(0,0)
  round 100 hole 50: 2(138,0)
  silkscreen extent -93,-161 215,113, body extent -69,-150 207,106, height 323

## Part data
C1 C24 C26 C32 C35 C37 C38 C137 C138: "CAP, CERM, 10 µF, 16 V,+/- 10%, X7R, 0805", Cap_Case=0805, Manufacturer="Samsung Electro-Mechanics", Supplier Part Number 1=1276-2872-1-ND, TempCo=X7R, Tolerance_%=10, Value2=16V, ValueDisplayed=10µF
C2 C3: "CAP, CERM, 1 µF, 16 V,+/- 10%, X7R, 0603", Cap_Case=0603, Manufacturer=MuRata, Supplier Part Number 1=490-3900-1-ND, TempCo=X7R, Tolerance_%=10, Value1="0.011 ohm", Value2=16V, ValueDisplayed=1µF
C4 C5 C34 C134: "CAP, CERM, 0.01 µF, 16 V,+/- 10%, X7R, 0603", Cap_Case=0603, Manufacturer=MuRata, Supplier Part Number 1=490-1525-1-ND, TempCo=X7R, Tolerance_%=10, Value2=16V, ValueDisplayed=0.01µF
C6 C7 C8: library part CMP-0007452-4, "CAP, CERM, 390 pF, 50 V, +/- 10%, X7R, 0603", Cap_Case=0603, Manufacturer=MuRata, Supplier Part Number 1=490-1555-1-ND, TempCo=X7R, Tolerance_%=10%, Value1=Unknown, Value2=50V, ValueDisplayed=390pF
C10 C11 C12 C13 C14 C15 C16 C17 C18 C19: "CAP, CERM, 47 µF, 10 V,+/- 20%, X7R, 1210", Cap_Case=1210, Manufacturer="Taiyo Yuden", Supplier Part Number 1=587-2783-1-ND, TempCo=X7R, Tolerance_%=20, Value2=10V, ValueDisplayed=47µF
C20 C21 C28 C29 C41 C42: "CAP, CERM, 22 µF, 10 V,+/- 10%, X7R, 1206", Cap_Case=1206, Manufacturer=MuRata, Supplier Part Number 1=490-10937-1-ND, TempCo=X7R, Tolerance_%=10, Value2=10V, ValueDisplayed=22µF
C22 C30 C39 C40 C43 C139 C140: "CAP, CERM, 0.1 µF, 16 V,+/- 10%, X7R, AEC-Q200 Grade 1, 0603", Cap_Case=0603, Manufacturer=MuRata, Supplier Part Number 1=490-8015-1-ND, TempCo=X7R, Tolerance_%=10, Value2=16V, ValueDisplayed=0.1µF
C23 C31 C44: "CAP, CERM, 3300 pF, 50 V,+/- 10%, X7R, AEC-Q200 Grade 1, 0402", Cap_Case=0402, Manufacturer=TDK, Supplier Part Number 1=445-6891-1-ND, TempCo=X7R, Tolerance_%=10, Value1="0.785178 ohm", Value2=50V, ValueDisplayed=3300pF
C25 C27 C33 C36 C45: library part CMP-0006237-2, "CAP, CERM, 0.1 uF, 16 V, +/- 10%, X7R, AEC-Q200 Grade 1, 0402", Cap_Case=0402, Manufacturer=Kemet, Supplier Part Number 1=399-6828-1-ND, TempCo=X7R, Tolerance_%=10%, Value1=Unknown, Value2=16V, ValueDisplayed=0.1uF
J1: library part CMP-0074913-1, "Terminal Block, 3.5mm Pitch, 2x1, TH", Color=Grey, Current_A=6A, Manufacturer="On-Shore Technology", Supplier Part Number 1=ED1514-ND, Voltage_V=150V
J2: "Header, 100mil, 4x1, TH", Manufacturer=Mill-Max, Supplier Part Number 1=ED7204-ND
J3: library part CMP-0055086-1, "Header, 100mil, 3x1, TH", Manufacturer=Mill-Max, Supplier Part Number 1=ED7203-ND
L1 L3 L4 L5: library part CMP-0087242-1, "Shielded Power Inductors", Manufacturer=Coilcraft
L2: "Ferrite Bead, 160 ohm @ 100 MHz, 6 A, 1206", Manufacturer="Laird-Signal Integrity Products", Supplier Part Number 1=240-2411-1-ND, Value1="0.018 ohm", Value2=6A, ValueDisplayed="160 ohm"
R1 R2 R3: "RES, 3.9, 5%, 0.125 W, 0805", Manufacturer=Vishay-Dale, Power_W=0.125, Supplier Part Number 1=541-3.9ACT-ND, TempCo="200 ppm/C", Tolerance_%=5, Value1=5%, Value2=0.125W, Value_Code=3R90, ValueDisplayed=3.9
R5 R13: "RES, 47, 5%, 0.1 W, 0603", Manufacturer=Vishay-Dale, Power_W=0.1, Supplier Part Number 1=541-47GCT-ND, TempCo="200 ppm/C", Tolerance_%=5, Value1=5%, Value2=0.1W, Value_Code=47R0, ValueDisplayed=47
R6: "RES, 19.6 k, 1%, 0.1 W, 0603", Manufacturer=Vishay-Dale, Power_W=0.1, Supplier Part Number 1=541-19.6KHCT-ND, TempCo="100 ppm/C", Tolerance_%=1, Value1=1%, Value2=0.1W, Value_Code=19k6, ValueDisplayed=19.6k
R7 R8: "RES, 2.2 k, 5%, 0.1 W, 0603", Manufacturer=Vishay-Dale, Power_W=0.1, Supplier Part Number 1=541-2.2KGCT-ND, TempCo="200 ppm/C", Tolerance_%=5, Value1=5%, Value2=0.1W, Value_Code=2k20, ValueDisplayed=2.2k
R9 R10: "RES, 100 k, 1%, 0.1 W, 0603", Manufacturer=Vishay-Dale, Power_W=0.1, Supplier Part Number 1=541-100KHCT-ND, TempCo="100 ppm/C", Tolerance_%=1, Value1=1%, Value2=0.1W, Value_Code=100k
R11 R15: library part CRCW0603100KFKEA, "RES, 100 k, 1%, 0.1 W, 0603", Manufacturer=Vishay-Dale, Power_W=0.1, Supplier Part Number 1=541-100KHCT-ND, TempCo="100 ppm/C", Tolerance_%=1, Value1=1%, Value2=0.1W, Value_Code=100k
R12 R112 R116: "RES, 5.49 k, 1%, 0.1 W, 0603", Manufacturer=Vishay-Dale, Power_W=0.1, Supplier Part Number 1=541-5.49KHCT-ND, TempCo="100 ppm/C", Tolerance_%=1, Value1=1%, Value2=0.1W, Value_Code=5k49, ValueDisplayed=5.49k
R14 R17: "RES, 10 k, 5%, 0.1 W, 0603", Manufacturer=Vishay-Dale, Power_W=0.1, Supplier Part Number 1=541-10KGCT-ND, TempCo="200 ppm/C", Tolerance_%=5, Value1=5%, Value2=0.1W, Value_Code=10k0, ValueDisplayed=10k
R101 R102: "RES, 2.00, 1%, 0.5 W, AEC-Q200 Grade 0, 1210", Manufacturer=Panasonic, Power_W=0.5, Supplier Part Number 1=P17258CT-ND, TempCo="100 ppm/C", Tolerance_%=1, Value1=1%, Value2=0.5W, Value_Code=2R00, ValueDisplayed=2.00
S1: library part CMP-0002178-2, "Switch, Slide, SPDT, 0.2A, GULL, 12V, SMD", CurrentRating_mA=200A, Manufacturer="Copal Electronics", Supplier Part Number 1=563-1318-1-ND
TP1: library part CMP-0055147-1, "Test Point, Multipurpose, Red, TH", Color=Red, Manufacturer=Keystone, Supplier Part Number 1=36-5010-ND
TP2 TP24: library part CMP-0055148-1, "Test Point, Multipurpose, Black, TH", Color=Black, Manufacturer=Keystone, Supplier Part Number 1=36-5011-ND
TP3 TP9 TP11: library part 5012, "Test Point, Multipurpose, White, TH", Color=White, Manufacturer=Keystone, Supplier Part Number 1=36-5012-ND
TP4 TP7 TP10 TP13 TP16 TP18 TP110 TP118: library part 1503-2, "Terminal, Turret, TH, Double", Manufacturer=Keystone, Supplier Part Number 1=1503-2K-ND
TP5 TP14: library part 5011, "Test Point, Multipurpose, Black, TH", Color=Black, Manufacturer=Keystone, Supplier Part Number 1=36-5011-ND
TP6 TP15: library part 5010, "Test Point, Multipurpose, Red, TH", Color=Red, Manufacturer=Keystone, Supplier Part Number 1=36-5010-ND
TP8 TP17: library part CMP-0055151-1, "Test Point, Multipurpose, Yellow, TH", Color=Yellow, Manufacturer=Keystone, Supplier Part Number 1=36-5014-ND
U1: library part CMP-0013900-3, "Four-Phase 8-A + 4-A + 4-A Buck Converters With Integrated Switches, RNF0026C (VQFN-HR-26)", Alternate Manufacturer="Texas Instruments", PartNumber=LP87563VRNFRQ1
U2 U12: library part CMP-0082614-1, "500-mA LDO With Power-Good, DRV0006A (WSON-6)", Alternate Manufacturer="Texas Instruments", Alternate PartNumber=TPS74501PDRVT, Operating Temperature Range="-40 to 125 C", PartNumber=TPS74501PBQWDRVRQ1

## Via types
v1: diameter 0.6, hole 0.3, Top Layer to Bottom Layer, tented both sides, 66 vias
v2: diameter 0.7, hole 0.4, Top Layer to Bottom Layer, 20 vias
v3: diameter 0.6, hole 0.3, Top Layer to Bottom Layer, 11 vias
v4: diameter 0.9, hole 0.5, Top Layer to Bottom Layer, 6 vias
v5: diameter 0.9, hole 0.5, Top Layer to Bottom Layer, tented top, 1 vias
v6: diameter 0.7, hole 0.3, Top Layer to Bottom Layer, 1 vias

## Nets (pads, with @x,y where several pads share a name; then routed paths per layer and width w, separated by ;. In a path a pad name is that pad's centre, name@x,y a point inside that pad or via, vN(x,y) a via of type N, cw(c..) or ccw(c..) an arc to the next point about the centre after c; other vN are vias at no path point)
1VD1: C20.1 C21.1 C22.2 C23.1 C28.1 C29.1 C30.2 C31.1 L3.2 L4.2 R5.2 TP4.1 TP6.1 | length 2.1
  Top Layer w0.4: 51.8,53.662 R5.2@53.874,53.662
3V3: C37.1 C39.2 C41.1 C42.1 C43.2 C44.1 L5.2 R13.2 R17.2 R101.1 TP13.1 TP15.1 U2.4 U2.6 | length 47.6
  Top Layer w0.3: 13.753,17.309 13.773,17.289 ; U2.6@13.773,16.512 13.773,17.289 ; U2.4@15.073,16.512 15.073,16.969 14.718,17.323 13.807,17.323 13.773,17.289
  Top Layer w0.4: R13.2@52.656,24.83 56.334,24.83 TP15.1@58.553,22.611 ; R17.2@60.287,15.24 60.287,14.083 v4(60.311,14.059)
  Layer 1 w0.4: TP13.1@48.006,6.477 58.553,17.024 TP15.1@58.553,22.611
  Layer 2 w0.4: TP13.1@48.006,6.477 49.125,5.358 51.61,5.358 v4(60.311,14.059)
  other v4: 10.311,20.074
  other v5: 20.828,11.43
5VS: C5.1 C10.1 C11.1 C12.1 C13.1 C14.1 C15.2 C16.1 C17.1 C18.1 C19.1 C24.1 C25.2 C26.1 C27.1 C32.1 C33.2 C35.1 C36.1 C45.1 L2.2 R9.1 R10.1 R11.1 S1.3 TP1.1 U1.9 U1.13 U1.18 U1.22 U1.26 | length 82.7
  Top Layer w0.25: C19.1@37.539,24.384 37.539,27.003 v1(38.222,27.686) 40.397,27.686 40.605,27.894 U1.22@40.605,29.123 ; C15.2@37.607,36.74 37.607,35.117 39.286,33.438 40.377,33.438 40.605,33.21 U1.13@40.605,32.203 ; 38.095,30.033 38.613,30.033 38.993,30.413 U1.18@39.705,30.413 ; U1.26@42.605,29.123 42.605,27.996 43.042,27.559 v1(45.085,27.559) 45.337,27.559 45.714,27.182 45.714,24.443 C16.1@45.773,24.384 ; U1.9@42.605,32.203 42.605,33.118 42.925,33.438 44.198,33.438 45.587,34.828 C10.1@45.587,36.74
  Top Layer w0.35: 37.686,30.033 38.095,30.033
  Top Layer w0.4: 30.607,31.306 30.67,31.369 R11.1@32.855,31.369 ; 30.734,29.337 R9.1@32.855,29.337 ; 30.888,27.813 R10.1@32.855,27.813 ; 35.972,30.465 36.368,30.861 C45.1@36.924,30.861 36.924,30.282 37.173,30.033 37.686,30.033
  Top Layer w0.6: TP1.1@26.96,37.473 TP1.1@27.336,37.849 ; 30.263,30.353 30.375,30.465 35.972,30.465 ; v4(67.351,27.951) S1.3@67.351,29.551
  Layer 2 w0.6: v2(35.052,18.795) 58.195,18.795 v4(67.351,27.951)
  other v1: 36.576,23.368 36.576,24.257 36.576,25.146 36.576,26.035 36.576,26.924 46.736,26.924 44.764,33.546 38.481,33.655 36.576,34.163 46.609,34.163 36.576,34.925 46.609,34.925 36.576,35.687 46.609,35.687 36.576,36.449 46.609,36.449 36.576,37.211 46.609,37.211
  other v2: 30.06,23.76 29.06,24.76 30.06,25.76 29.06,26.76 30.06,27.76 29.06,28.76 27.06,40.76 29.06,40.76 28.06,41.76 27.06,42.76 29.06,42.76 28.06,43.76 27.06,44.76 29.06,44.76 28.06,45.76 27.06,46.76 29.06,46.76 28.06,47.76 29.06,48.76
  other v3: 46.736,23.368 46.736,24.257 46.736,25.146 46.736,26.035
CLKIN: R14.1 U1.3 | length 5.4
  Top Layer w0.25: U1.3@43.505,29.913 48.798,29.913 R14.1@48.857,29.972
EN1: R15.2 S1.2 U1.7 | length 23.4
  Top Layer w0.25: U1.7@43.505,31.913 43.555,31.963 43.911,31.963 43.986,32.038 44.013,32.038 44.308,32.334 47.445,32.334 ; 47.452,32.327 47.445,32.334 ; R15.2@55.88,31.228 55.88,32.004 54.674,33.21 52.298,33.21 50.972,31.884 48.237,31.884 47.787,32.334 47.445,32.334
  Top Layer w0.4: R15.2@55.88,31.228 58.774,31.228 S1.2@62.951,27.051
GND: C1.2 C2.2 C3.2 C4.2 C5.2 C10.2 C11.2 C12.2 C13.2 C14.2 C15.1 C16.2 C17.2 C18.2 C19.2 C20.2 C21.2 C22.1 C23.2 C24.2 C25.1 C26.2 C27.2 C28.2 C29.2 C30.1 C31.2 C32.2 C33.1 C35.2 C36.2 C37.2 C38.2 C39.1 C40.1 C41.2 C42.2 C43.1 C44.2 C45.2 C137.2 C138.2 C139.1 C140.1 J1.2 J2.1 J3.1 R1.1 R2.1 R3.1 R12.1 R14.2 R15.1 R112.1 S1.1 TP2.1 TP5.1 TP7.1 TP14.1 TP16.1 TP18.1 TP24.1 TP118.1 U1.4 U1.11 U1.14 U1.17 U1.21 U1.24 U1.27 U2.3 U2.7@14.423,15.537 U12.3 U12.7@30.913,15.823 | length 95.8
  Top Layer w0.25: v1(35.433,33.02) 35.472,32.981 38.858,32.981 39.351,32.488 U1.14@39.705,32.488 ; v1(37.075,28.358) 38.833,28.358 39.313,28.838 U1.21@39.705,28.838 ; C45.2@37.924,30.861 37.976,30.913 v1@38.352,30.913 ; C45.2@38.21,30.771 v1@38.352,30.913 ; C19.2@40.507,24.421 41.605,25.519 v1@41.605,25.63 ; C15.1@40.507,36.74 41.589,35.658 v1@41.605,35.658 ; U1.27@40.607,30.873 40.251,30.873 40.211,30.913 U1.17@39.705,30.913 v1@38.352,30.913 ; U1.27@42.486,30.466 42.944,30.466 42.997,30.413 U1.4@43.505,30.413 45.399,30.413 v1(45.593,30.607) ; C10.2@42.687,36.74 v1@41.605,35.658 ; C16.2@42.814,24.421 v1@41.605,25.63 ; v1@41.605,25.63 U1.24@41.605,29.123 v3(41.605,30.663) U1.11@41.605,32.203 v1@41.605,35.658
  Top Layer w0.4: TP16.1@40.38,7.112 TP16.1@41.015,6.477
  Top Layer w0.6: TP14.1@36.195,7.112 TP16.1@40.38,7.112 ; v1(45.593,30.607) v1(46.455,30.607)
  Layer 1 w0.4: v1(35.433,33.02) 35.472,32.981 38.165,32.981 38.191,32.955 38.771,32.955 38.797,32.981 38.858,32.981 39.055,32.784 50.856,32.784 54.001,35.928 54.001,37.131 57.924,41.053 57.924,44.565 57.019,45.47 57.019,46.854 57.924,47.759 57.924,51.493 56.605,52.812 55.924,52.812 55.548,53.188 52.279,53.188 50.244,51.152 44.479,51.152 TP7.1@41.529,54.102
  Layer 2 w0.4: v1@37.103,28.386 v1(37.075,28.358) 37.075,29.379 v1(38.354,30.658)
  other v1: 43.561,20.066 45.212,20.066 46.863,20.066 48.641,20.066 41.656,20.193 41.656,21.971 41.656,22.86 41.656,23.749 41.656,24.638 41.656,25.527 41.402,26.416 41.402,27.305 55.88,28.878 51.207,29.972 41.597,33.946 41.597,34.708 41.597,35.47 41.597,36.232 41.597,36.994 41.597,37.756 41.597,38.518 41.597,39.28 41.597,40.042 33.401,41.021 35.306,41.021 36.957,41.021 38.862,41.021 39.751,41.021 40.767,41.021 42.291,41.021 43.307,41.021 44.45,41.021 46.101,41.021 47.879,41.021 49.657,41.021
  other v3: 13.94,15.54 14.905,15.54 30.429,15.824 31.394,15.824 40.735,30.663 42.475,30.663
  other v4: 32.904,33.063
GPIO2: J3.3 R17.1 U1.15 U12.4 | length 59.9
  Top Layer w0.25: v6(31.394,17.784) 31.563,17.615 U12.4@31.563,16.798 ; v1(35.682,32.203) 35.972,31.913 U1.15@39.705,31.913
  Top Layer w0.4: R17.1@61.887,15.24 62.014,15.367 J3.3@65.151,15.367
  Layer 2 w0.4: v6@31.413,17.784 30.913,18.284 30.913,27.434 v1(35.682,32.203)
  Bottom Layer w0.25: v6(31.394,17.784) v6@31.413,17.784
  Bottom Layer w0.4: v6(31.394,17.784) 33.26,15.918 64.6,15.918 J3.3@65.151,15.367
GPIO3: J3.2 U1.2 | length 26.4
  Top Layer w0.25: U1.2@43.505,29.413 46.649,29.413 46.939,29.123 v1(47.033,29.123)
  Bottom Layer w0.4: v1(47.033,29.123) 49.088,29.123 60.304,17.907 J3.2@65.151,17.907
NetC1_1: C1.1 C2.1 J1.1 L1.1
NetC3_1: C3.1 C4.1 L1.2 L2.1
NetC6_2: C6.2 R1.2
NetC7_2: C7.2 R2.2
NetC8_2: C8.2 R3.2
NetC34_1: C34.1 C38.1 C40.2 R6.2 TP10.1 U2.1 | length 1.1
  Top Layer w0.3: 13.773,13.509 U2.1@13.773,14.562
NetC34_2: C34.2 R6.1 R12.2 U2.2 | length 5.2
  Top Layer w0.3: U2.2@14.423,14.562 14.423,14.224 15.439,13.208 C34.2@15.439,12.784
  Top Layer w0.4: C34.2@15.439,12.784 R6.1@15.439,11.26 16.887,11.26 R12.2@16.925,11.222
NetC134_1: C134.1 C138.1 C140.2 R116.2 TP110.1 U12.1 | length 12.8
  Top Layer w0.3: C138.1@26.804,12.407 27.985,12.407 C140.2@28.582,13.004 C140.2@28.663,13.085 ; U12.1@30.263,14.848 30.263,13.104 C134.1@30.282,13.085 R116.2@30.282,11.51
  Top Layer w0.8: C138.1@26.804,12.407 26.804,10.4 30.226,6.978 TP110.1@30.226,6.477
NetC134_2: C134.2 R112.2 R116.1 U12.2 | length 5.3
  Top Layer w0.3: U12.2@30.913,14.848 30.913,14.469 31.882,13.5 C134.2@31.882,13.085
  Top Layer w0.4: C134.2@31.882,13.085 R116.1@31.882,11.51 32.022,11.65 R112.2@33.408,11.65
NetC137_1: C137.1 C139.2 R102.2 U12.6 | length 2.9
  Top Layer w0.3: 30.099,17.763 30.263,17.599 U12.6@30.263,16.798
  Top Layer w0.4: C139.2@28.582,18.584 29.278,18.584 30.099,17.763
NetJ2_4: J2.4 R7.1 R8.1 | length 16.3
  Top Layer w0.4: v1(52.832,28.878) R8.1@52.832,29.628 ; v1(54.356,28.878) R7.1@54.356,29.628
  Bottom Layer w0.4: v1(52.832,28.878) v1(54.356,28.878) 54.89,28.878 55.59,28.178 56.931,28.178 62.377,33.624 J2.4@65.113,33.624
NetR5_1: R5.1 TP8.1 U1.8 | length 33.5
  Top Layer w0.25: U1.8@43.505,32.488 43.826,32.488 44.122,32.784 48.585,32.784
  Top Layer w0.4: 48.585,32.784 50.856,32.784 v4(54.851,36.778) ; R5.1@55.474,53.662 v4(56.605,53.662)
  Layer 1 w0.4: v4(54.851,36.778) 58.524,40.451 58.524,46.231 58.524,51.743 v4(56.605,53.662)
NetR13_1: R13.1 TP17.1 U1.1 | length 16.2
  Top Layer w0.25: U1.1@43.505,28.838 46.363,28.838 46.753,28.448 47.227,28.448 48.932,28.448
  Top Layer w0.4: 48.932,28.448 50.638,28.448 R13.1@52.656,26.43 53.023,26.797 TP17.1@58.547,26.797
NetR101_2: R101.2 R102.1 | length 3
  Top Layer w1: R101.2@22.639,14.594 R102.1@22.639,17.59
nINT: R9.2 U1.19 | length 5.5
  Top Layer w0.2: R9.2@34.455,29.337 35.205,29.337 35.379,29.511 38.709,29.511 39.111,29.913 U1.19@39.705,29.913
nRST: R10.2 U1.20 | length 5.9
  Top Layer w0.2: R10.2@34.455,27.813 35.682,27.813 36.827,28.958 38.832,28.958 39.287,29.413 U1.20@39.705,29.413
PGOOD: R11.2 U1.16 | length 5.3
  Top Layer w0.2: 35.527,31.463 36.689,31.463
  Top Layer w0.25: 36.689,31.463 36.691,31.461 38.915,31.461 38.963,31.413 U1.16@39.705,31.413
  Top Layer w0.4: R11.2@34.455,31.496 34.488,31.463 35.527,31.463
